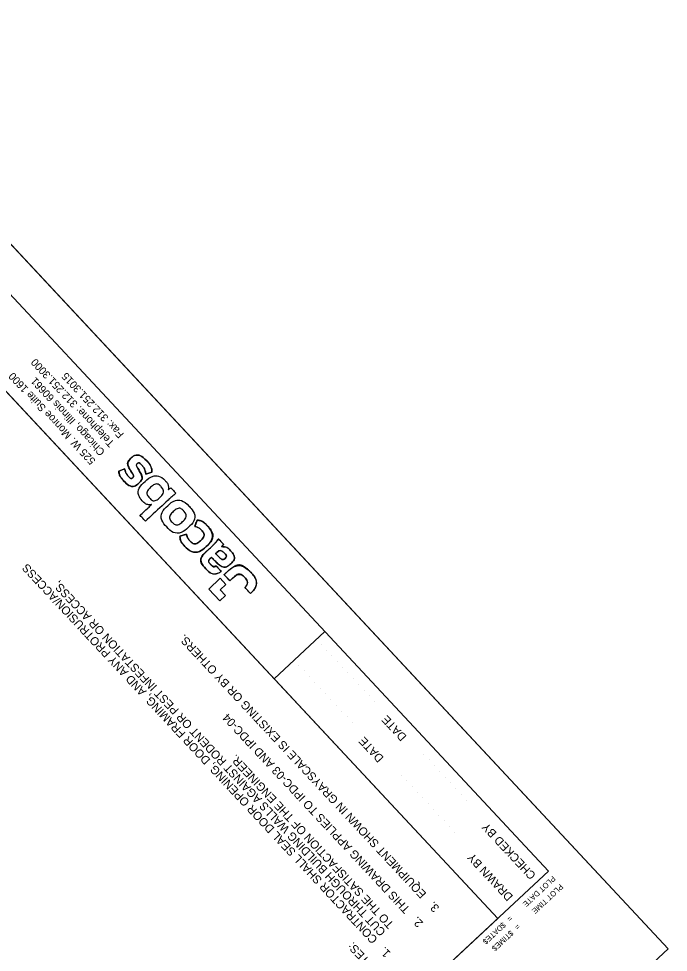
# Model space of a CAD drawing. Extents: x 1121979 to 1130574, y 1838676 to 1848573.
# Drawn here: x 1129668.15 to 1129686.91, y 1839365.55 to 1839392.53 of the extents above; entities that cross this region are included whole.
import ezdxf

# ---------------------------------------------------------------- set-up
doc = ezdxf.new("R2010")
doc.units = 0
for name, color, linetype in [('GE-LOG-JEG', 7, 'Continuous'), ('GE-NOT-Notes', 7, 'Continuous'), ('GE-SHT-Clip Border', 7, 'Continuous'), ('GE-SHT-General', 7, 'Continuous'), ('GE-SHT-Plot Border', 7, 'Continuous'), ('HS_Title', 7, 'Continuous')]:
    doc.layers.add(name, color=color, linetype=linetype)

msp = doc.modelspace()

# ---------------------------------------------------------------- linework, layer by layer
at = {"layer": 'GE-LOG-JEG'}
for p, q in [((1129671.632, 1839379.468), (1129671.579, 1839379.556)), ((1129671.212, 1839379.521), (1129671.037, 1839379.46)), ((1129671.38, 1839379.472), (1129671.437, 1839379.377)), ((1129671.82, 1839379.365), (1129671.995, 1839379.429)), ((1129673.304, 1839378.04), (1129673.233, 1839377.862)), ((1129672.999, 1839377.632), (1129672.806, 1839377.575)), ((1129674.064, 1839377.344), (1129673.917, 1839377.5)), ((1129673.745, 1839377.301), (1129673.551, 1839377.12)), ((1129673.999, 1839376.559), (1129673.853, 1839376.716)), ((1129673.971, 1839376.362), (1129673.637, 1839376.05)), ((1129674.135, 1839376.186), (1129673.971, 1839376.362)), ((1129673.637, 1839376.05), (1129673.957, 1839375.707)), ((1129673.968, 1839376.03), (1129674.135, 1839376.186)), ((1129674.124, 1839375.862), (1129673.968, 1839376.03)), ((1129674.68, 1839376.092), (1129674.843, 1839375.917)), ((1129673.957, 1839375.707), (1129674.124, 1839375.862))]:
    msp.add_line(p, q, dxfattribs=at)
for points in [[(1129673.946, 1839376.961), (1129673.83, 1839377.074), (1129673.869, 1839377.11)], [(1129673.689, 1839376.942), (1129673.714, 1839376.966), (1129673.863, 1839376.821)], [(1129674.187, 1839376.563), (1129674.082, 1839376.465), (1129674.246, 1839376.289), (1129674.351, 1839376.387)], [(1129674.135, 1839376.186), (1129673.971, 1839376.362), (1129673.637, 1839376.05), (1129673.957, 1839375.707), (1129674.124, 1839375.862), (1129673.968, 1839376.03), (1129674.135, 1839376.186)]]:
    msp.add_lwpolyline(points, dxfattribs=at)
for points, degree in [([(1129671.848, 1839379.754), (1129671.7, 1839379.913), (1129671.514, 1839379.947), (1129671.395, 1839379.836), (1129671.292, 1839379.74), (1129671.288, 1839379.624), (1129671.38, 1839379.472), (1129671.38, 1839379.472), (1129671.437, 1839379.377), (1129671.437, 1839379.377), (1129671.466, 1839379.329), (1129671.468, 1839379.291), (1129671.445, 1839379.269), (1129671.414, 1839379.24), (1129671.366, 1839379.252), (1129671.32, 1839379.302), (1129671.268, 1839379.357), (1129671.235, 1839379.425), (1129671.212, 1839379.521), (1129671.212, 1839379.521), (1129671.037, 1839379.46), (1129671.037, 1839379.46), (1129671.049, 1839379.365), (1129671.098, 1839379.266), (1129671.178, 1839379.181), (1129671.323, 1839379.025), (1129671.497, 1839378.998), (1129671.622, 1839379.114), (1129671.72, 1839379.206), (1129671.723, 1839379.319), (1129671.632, 1839379.468), (1129671.632, 1839379.468), (1129671.579, 1839379.556), (1129671.579, 1839379.556), (1129671.543, 1839379.616), (1129671.542, 1839379.646), (1129671.571, 1839379.673), (1129671.602, 1839379.703), (1129671.653, 1839379.685), (1129671.712, 1839379.622), (1129671.76, 1839379.57), (1129671.803, 1839379.468), (1129671.82, 1839379.365), (1129671.82, 1839379.365), (1129671.995, 1839379.429), (1129671.995, 1839379.429), (1129671.995, 1839379.53), (1129671.939, 1839379.654), (1129671.848, 1839379.754)], 3), ([(1129671.848, 1839379.754), (1129671.7, 1839379.913), (1129671.514, 1839379.947), (1129671.395, 1839379.836), (1129671.292, 1839379.74), (1129671.288, 1839379.624), (1129671.38, 1839379.472)], 3), ([(1129671.579, 1839379.556), (1129671.543, 1839379.616), (1129671.542, 1839379.646), (1129671.571, 1839379.673), (1129671.602, 1839379.703), (1129671.653, 1839379.685), (1129671.712, 1839379.622), (1129671.76, 1839379.57), (1129671.803, 1839379.468), (1129671.82, 1839379.365)], 3), ([(1129671.995, 1839379.429), (1129671.995, 1839379.53), (1129671.939, 1839379.654), (1129671.848, 1839379.754)], 2), ([(1129671.037, 1839379.46), (1129671.049, 1839379.365), (1129671.098, 1839379.266), (1129671.178, 1839379.181), (1129671.323, 1839379.025), (1129671.497, 1839378.998), (1129671.622, 1839379.114), (1129671.72, 1839379.206), (1129671.723, 1839379.319), (1129671.632, 1839379.468)], 3), ([(1129671.437, 1839379.377), (1129671.466, 1839379.329), (1129671.468, 1839379.291), (1129671.445, 1839379.269), (1129671.414, 1839379.24), (1129671.366, 1839379.252), (1129671.32, 1839379.302), (1129671.268, 1839379.357), (1129671.235, 1839379.425), (1129671.212, 1839379.521)], 3), ([(1129672.379, 1839379.184), (1129672.243, 1839379.33), (1129672.003, 1839379.35), (1129671.799, 1839379.16), (1129671.602, 1839378.976), (1129671.588, 1839378.742), (1129671.729, 1839378.59), (1129671.806, 1839378.508), (1129671.899, 1839378.478), (1129671.993, 1839378.493), (1129671.993, 1839378.493), (1129671.654, 1839378.177), (1129671.654, 1839378.177), (1129671.654, 1839378.177), (1129671.809, 1839378.011), (1129671.809, 1839378.011), (1129671.809, 1839378.011), (1129672.512, 1839378.666), (1129672.512, 1839378.666), (1129672.57, 1839378.72), (1129672.623, 1839378.765), (1129672.689, 1839378.818), (1129672.689, 1839378.818), (1129672.543, 1839378.974), (1129672.543, 1839378.974), (1129672.517, 1839378.954), (1129672.489, 1839378.933), (1129672.46, 1839378.908), (1129672.481, 1839379.011), (1129672.449, 1839379.109), (1129672.379, 1839379.184), (1129672.379, 1839379.184), (1129672.379, 1839379.184), (1129672.379, 1839379.184)], 3), ([(1129672.379, 1839379.184), (1129672.243, 1839379.33), (1129672.003, 1839379.35), (1129671.799, 1839379.16), (1129671.602, 1839378.976), (1129671.588, 1839378.742), (1129671.729, 1839378.59), (1129671.806, 1839378.508), (1129671.899, 1839378.478), (1129671.993, 1839378.493), (1129671.993, 1839378.493), (1129671.654, 1839378.177), (1129671.654, 1839378.177), (1129671.654, 1839378.177), (1129671.809, 1839378.011), (1129671.809, 1839378.011), (1129671.809, 1839378.011), (1129672.512, 1839378.666), (1129672.512, 1839378.666), (1129672.57, 1839378.72), (1129672.623, 1839378.765), (1129672.689, 1839378.818), (1129672.689, 1839378.818), (1129672.543, 1839378.974), (1129672.543, 1839378.974), (1129672.517, 1839378.954), (1129672.489, 1839378.933), (1129672.46, 1839378.908), (1129672.481, 1839379.011), (1129672.449, 1839379.109), (1129672.379, 1839379.184), (1129672.379, 1839379.184), (1129672.379, 1839379.184), (1129672.379, 1839379.184)], 3), ([(1129672.265, 1839379.004), (1129672.347, 1839378.916), (1129672.336, 1839378.8), (1129672.229, 1839378.699), (1129672.122, 1839378.599), (1129672.005, 1839378.596), (1129671.923, 1839378.684), (1129671.841, 1839378.773), (1129671.852, 1839378.889), (1129671.959, 1839378.989), (1129672.066, 1839379.089), (1129672.183, 1839379.092), (1129672.265, 1839379.004), (1129672.265, 1839379.004), (1129672.265, 1839379.004), (1129672.265, 1839379.004)], 3), ([(1129672.265, 1839379.004), (1129672.347, 1839378.916), (1129672.336, 1839378.8), (1129672.229, 1839378.699), (1129672.122, 1839378.599), (1129672.005, 1839378.596), (1129671.923, 1839378.684), (1129671.841, 1839378.773), (1129671.852, 1839378.889), (1129671.959, 1839378.989), (1129672.066, 1839379.089), (1129672.183, 1839379.092), (1129672.265, 1839379.004), (1129672.265, 1839379.004), (1129672.265, 1839379.004), (1129672.265, 1839379.004)], 3), ([(1129673.075, 1839378.438), (1129672.9, 1839378.626), (1129672.651, 1839378.644), (1129672.453, 1839378.459), (1129672.255, 1839378.275), (1129672.25, 1839378.031), (1129672.425, 1839377.843), (1129672.597, 1839377.659), (1129672.855, 1839377.653), (1129673.042, 1839377.827), (1129673.234, 1839378.006), (1129673.247, 1839378.253), (1129673.075, 1839378.438), (1129673.075, 1839378.438), (1129673.075, 1839378.438), (1129673.075, 1839378.438)], 3), ([(1129673.075, 1839378.438), (1129672.9, 1839378.626), (1129672.651, 1839378.644), (1129672.453, 1839378.459), (1129672.255, 1839378.275), (1129672.25, 1839378.031), (1129672.425, 1839377.843), (1129672.597, 1839377.659), (1129672.855, 1839377.653), (1129673.042, 1839377.827), (1129673.234, 1839378.006), (1129673.247, 1839378.253), (1129673.075, 1839378.438), (1129673.075, 1839378.438), (1129673.075, 1839378.438), (1129673.075, 1839378.438)], 3), ([(1129672.919, 1839378.303), (1129673.001, 1839378.215), (1129672.99, 1839378.099), (1129672.882, 1839377.999), (1129672.775, 1839377.899), (1129672.658, 1839377.896), (1129672.576, 1839377.984), (1129672.494, 1839378.072), (1129672.505, 1839378.188), (1129672.612, 1839378.288), (1129672.72, 1839378.388), (1129672.837, 1839378.391), (1129672.919, 1839378.303), (1129672.919, 1839378.303), (1129672.919, 1839378.303), (1129672.919, 1839378.303)], 3), ([(1129672.919, 1839378.303), (1129673.001, 1839378.215), (1129672.99, 1839378.099), (1129672.882, 1839377.999), (1129672.775, 1839377.899), (1129672.658, 1839377.896), (1129672.576, 1839377.984), (1129672.494, 1839378.072), (1129672.505, 1839378.188), (1129672.612, 1839378.288), (1129672.72, 1839378.388), (1129672.837, 1839378.391), (1129672.919, 1839378.303), (1129672.919, 1839378.303), (1129672.919, 1839378.303), (1129672.919, 1839378.303)], 3), ([(1129673.586, 1839377.89), (1129673.508, 1839377.973), (1129673.399, 1839378.032), (1129673.304, 1839378.04), (1129673.304, 1839378.04), (1129673.233, 1839377.862), (1129673.233, 1839377.862), (1129673.305, 1839377.843), (1129673.38, 1839377.802), (1129673.422, 1839377.756), (1129673.51, 1839377.662), (1129673.502, 1839377.542), (1129673.399, 1839377.445), (1129673.298, 1839377.352), (1129673.176, 1839377.348), (1129673.079, 1839377.452), (1129673.039, 1839377.495), (1129673.011, 1839377.564), (1129672.999, 1839377.632), (1129672.999, 1839377.632), (1129672.806, 1839377.575), (1129672.806, 1839377.575), (1129672.809, 1839377.48), (1129672.853, 1839377.385), (1129672.928, 1839377.304), (1129673.123, 1839377.095), (1129673.385, 1839377.112), (1129673.558, 1839377.274), (1129673.756, 1839377.458), (1129673.768, 1839377.695), (1129673.586, 1839377.89), (1129673.586, 1839377.89), (1129673.586, 1839377.89), (1129673.586, 1839377.89)], 3), ([(1129673.586, 1839377.89), (1129673.508, 1839377.973), (1129673.399, 1839378.032), (1129673.304, 1839378.04)], 2), ([(1129672.806, 1839377.575), (1129672.809, 1839377.48), (1129672.853, 1839377.385), (1129672.928, 1839377.304), (1129673.123, 1839377.095), (1129673.385, 1839377.112), (1129673.558, 1839377.274), (1129673.756, 1839377.458), (1129673.768, 1839377.695), (1129673.586, 1839377.89)], 3), ([(1129673.233, 1839377.862), (1129673.305, 1839377.843), (1129673.38, 1839377.802), (1129673.422, 1839377.756), (1129673.51, 1839377.662), (1129673.502, 1839377.542), (1129673.399, 1839377.445), (1129673.298, 1839377.352), (1129673.176, 1839377.348), (1129673.079, 1839377.452), (1129673.039, 1839377.495), (1129673.011, 1839377.564), (1129672.999, 1839377.632)], 3), ([(1129674.064, 1839377.344), (1129674.064, 1839377.344), (1129673.917, 1839377.5), (1129673.917, 1839377.5), (1129673.878, 1839377.441), (1129673.803, 1839377.355), (1129673.745, 1839377.301), (1129673.745, 1839377.301), (1129673.551, 1839377.12), (1129673.551, 1839377.12), (1129673.401, 1839376.981), (1129673.396, 1839376.802), (1129673.549, 1839376.638), (1129673.714, 1839376.461), (1129673.898, 1839376.488), (1129673.999, 1839376.559), (1129673.999, 1839376.559), (1129673.853, 1839376.716), (1129673.853, 1839376.716), (1129673.804, 1839376.689), (1129673.746, 1839376.7), (1129673.69, 1839376.76), (1129673.635, 1839376.82), (1129673.629, 1839376.886), (1129673.689, 1839376.942), (1129673.689, 1839376.942), (1129673.714, 1839376.966), (1129673.714, 1839376.966), (1129673.714, 1839376.966), (1129673.863, 1839376.821), (1129673.863, 1839376.821), (1129674.021, 1839376.668), (1129674.163, 1839376.679), (1129674.271, 1839376.78), (1129674.388, 1839376.889), (1129674.381, 1839377.037), (1129674.263, 1839377.164), (1129674.175, 1839377.258), (1129674.073, 1839377.276), (1129674.007, 1839377.271), (1129674.03, 1839377.297), (1129674.05, 1839377.324), (1129674.064, 1839377.344), (1129674.064, 1839377.344), (1129674.064, 1839377.344), (1129674.064, 1839377.344)], 3), ([(1129673.917, 1839377.5), (1129673.878, 1839377.441), (1129673.803, 1839377.355), (1129673.745, 1839377.301)], 2), ([(1129673.551, 1839377.12), (1129673.401, 1839376.981), (1129673.396, 1839376.802), (1129673.549, 1839376.638), (1129673.714, 1839376.461), (1129673.898, 1839376.488), (1129673.999, 1839376.559)], 3), ([(1129673.869, 1839377.11), (1129673.95, 1839377.185), (1129674.04, 1839377.141), (1129674.092, 1839377.086), (1129674.145, 1839377.029), (1129674.152, 1839376.978), (1129674.107, 1839376.935), (1129674.067, 1839376.898), (1129674.014, 1839376.896), (1129673.946, 1839376.961), (1129673.946, 1839376.961), (1129673.83, 1839377.074), (1129673.83, 1839377.074), (1129673.83, 1839377.074), (1129673.869, 1839377.11), (1129673.869, 1839377.11)], 3), ([(1129673.863, 1839376.821), (1129674.021, 1839376.668), (1129674.163, 1839376.679), (1129674.271, 1839376.78), (1129674.388, 1839376.889), (1129674.381, 1839377.037), (1129674.263, 1839377.164), (1129674.175, 1839377.258), (1129674.073, 1839377.276), (1129674.007, 1839377.271)], 3), ([(1129673.869, 1839377.11), (1129673.95, 1839377.185), (1129674.04, 1839377.141), (1129674.092, 1839377.086), (1129674.145, 1839377.029), (1129674.152, 1839376.978), (1129674.107, 1839376.935), (1129674.067, 1839376.898), (1129674.014, 1839376.896), (1129673.946, 1839376.961)], 3), ([(1129674.007, 1839377.271), (1129674.03, 1839377.297), (1129674.05, 1839377.324), (1129674.064, 1839377.344)], 2), ([(1129673.853, 1839376.716), (1129673.804, 1839376.689), (1129673.746, 1839376.7), (1129673.69, 1839376.76), (1129673.635, 1839376.82), (1129673.629, 1839376.886), (1129673.689, 1839376.942)], 3), ([(1129674.844, 1839376.54), (1129674.655, 1839376.743), (1129674.385, 1839376.748), (1129674.187, 1839376.563), (1129674.187, 1839376.563), (1129674.082, 1839376.465), (1129674.082, 1839376.465), (1129674.082, 1839376.465), (1129674.246, 1839376.289), (1129674.246, 1839376.289), (1129674.246, 1839376.289), (1129674.351, 1839376.387), (1129674.351, 1839376.387), (1129674.455, 1839376.484), (1129674.582, 1839376.483), (1129674.675, 1839376.383), (1129674.763, 1839376.289), (1129674.755, 1839376.179), (1129674.68, 1839376.092), (1129674.68, 1839376.092), (1129674.843, 1839375.917), (1129674.843, 1839375.917), (1129675.017, 1839376.097), (1129675.023, 1839376.349), (1129674.844, 1839376.54), (1129674.844, 1839376.54), (1129674.844, 1839376.54), (1129674.844, 1839376.54)], 3), ([(1129674.844, 1839376.54), (1129674.655, 1839376.743), (1129674.385, 1839376.748), (1129674.187, 1839376.563)], 2), ([(1129674.351, 1839376.387), (1129674.455, 1839376.484), (1129674.582, 1839376.483), (1129674.675, 1839376.383), (1129674.763, 1839376.289), (1129674.755, 1839376.179), (1129674.68, 1839376.092)], 3), ([(1129674.843, 1839375.917), (1129675.017, 1839376.097), (1129675.023, 1839376.349), (1129674.844, 1839376.54)], 2)]:
    msp.add_open_spline(points, degree=degree, dxfattribs=at)
at = {"layer": 'GE-NOT-Notes'}
msp.add_line((1129686.907, 1839365.651), (1129640.533, 1839415.386), dxfattribs=at)
at = {"layer": 'GE-SHT-Clip Border'}
msp.add_lwpolyline([(1129652.729, 1839339.252), (1129609.766, 1839385.33), (1129639.021, 1839412.608), (1129681.985, 1839366.531)], close=True, dxfattribs=at)
msp.add_lwpolyline([(1129652.729, 1839339.252), (1129609.766, 1839385.33), (1129639.021, 1839412.608), (1129681.985, 1839366.531)], close=True, dxfattribs=at)
msp.add_lwpolyline([(1129652.729, 1839339.252), (1129609.766, 1839385.33), (1129639.021, 1839412.608), (1129681.985, 1839366.531)], close=True, dxfattribs=at)
at = {"layer": 'GE-SHT-General'}
for p, q in [((1129639.021, 1839412.608), (1129681.985, 1839366.531)), ((1129676.986, 1839374.824), (1129675.524, 1839373.46)), ((1129676.884, 1839374.454), (1129676.884, 1839374.454)), ((1129677.039, 1839374.288), (1129677.039, 1839374.288)), ((1129677.194, 1839374.122), (1129677.194, 1839374.122)), ((1129677.348, 1839373.957), (1129677.348, 1839373.957)), ((1129676.238, 1839373.851), (1129676.238, 1839373.851)), ((1129676.393, 1839373.685), (1129676.393, 1839373.685)), ((1129677.503, 1839373.791), (1129677.503, 1839373.791)), ((1129677.657, 1839373.625), (1129677.657, 1839373.625)), ((1129676.547, 1839373.52), (1129676.547, 1839373.52)), ((1129676.702, 1839373.354), (1129676.702, 1839373.354)), ((1129677.812, 1839373.459), (1129677.812, 1839373.459)), ((1129676.856, 1839373.188), (1129676.856, 1839373.188)), ((1129677.966, 1839373.293), (1129677.966, 1839373.293)), ((1129678.121, 1839373.128), (1129678.121, 1839373.128)), ((1129677.011, 1839373.022), (1129677.011, 1839373.022)), ((1129677.166, 1839372.856), (1129677.166, 1839372.856)), ((1129678.276, 1839372.962), (1129678.276, 1839372.962)), ((1129678.43, 1839372.796), (1129678.43, 1839372.796)), ((1129677.32, 1839372.691), (1129677.32, 1839372.691)), ((1129677.475, 1839372.525), (1129677.475, 1839372.525)), ((1129677.629, 1839372.359), (1129677.629, 1839372.359)), ((1129677.784, 1839372.193), (1129677.784, 1839372.193)), ((1129679.844, 1839371.28), (1129679.844, 1839371.28)), ((1129679.998, 1839371.114), (1129679.998, 1839371.114)), ((1129680.153, 1839370.948), (1129680.153, 1839370.948)), ((1129679.197, 1839370.677), (1129679.197, 1839370.677)), ((1129680.308, 1839370.783), (1129680.308, 1839370.783)), ((1129679.352, 1839370.511), (1129679.352, 1839370.511)), ((1129680.462, 1839370.617), (1129680.462, 1839370.617)), ((1129680.617, 1839370.451), (1129680.617, 1839370.451)), ((1129679.507, 1839370.346), (1129679.507, 1839370.346)), ((1129679.661, 1839370.18), (1129679.661, 1839370.18)), ((1129680.771, 1839370.285), (1129680.771, 1839370.285)), ((1129680.926, 1839370.119), (1129680.926, 1839370.119)), ((1129679.816, 1839370.014), (1129679.816, 1839370.014)), ((1129679.97, 1839369.848), (1129679.97, 1839369.848)), ((1129681.08, 1839369.954), (1129681.08, 1839369.954)), ((1129680.125, 1839369.683), (1129680.125, 1839369.683)), ((1129680.279, 1839369.517), (1129680.279, 1839369.517)), ((1129680.434, 1839369.351), (1129680.434, 1839369.351)), ((1129680.589, 1839369.185), (1129680.589, 1839369.185)), ((1129680.743, 1839369.019), (1129680.743, 1839369.019)), ((1129686.907, 1839365.651), (1129686.907, 1839365.651)), ((1129686.907, 1839365.651), (1129686.907, 1839365.651)), ((1129686.907, 1839365.651), (1129686.907, 1839365.651)), ((1129686.907, 1839365.651), (1129686.907, 1839365.651)), ((1129686.907, 1839365.651), (1129686.907, 1839365.651)), ((1129686.907, 1839365.651), (1129686.907, 1839365.651)), ((1129686.907, 1839365.651), (1129686.907, 1839365.651)), ((1129686.907, 1839365.651), (1129686.907, 1839365.651)), ((1129686.907, 1839365.651), (1129686.907, 1839365.651)), ((1129686.907, 1839365.651), (1129686.907, 1839365.651)), ((1129686.907, 1839365.651), (1129686.907, 1839365.651)), ((1129686.907, 1839365.651), (1129686.907, 1839365.651)), ((1129686.907, 1839365.651), (1129686.907, 1839365.651)), ((1129686.907, 1839365.651), (1129686.907, 1839365.651)), ((1129686.907, 1839365.651), (1129686.907, 1839365.651)), ((1129686.907, 1839365.651), (1129686.907, 1839365.651)), ((1129686.907, 1839365.651), (1129686.907, 1839365.651)), ((1129686.907, 1839365.651), (1129686.907, 1839365.651)), ((1129686.907, 1839365.651), (1129686.907, 1839365.651)), ((1129686.907, 1839365.651), (1129686.907, 1839365.651)), ((1129686.907, 1839365.651), (1129686.907, 1839365.651)), ((1129686.907, 1839365.651), (1129686.907, 1839365.651)), ((1129686.907, 1839365.651), (1129686.907, 1839365.651)), ((1129686.907, 1839365.651), (1129686.907, 1839365.651)), ((1129686.907, 1839365.651), (1129686.907, 1839365.651)), ((1129686.907, 1839365.651), (1129686.907, 1839365.651)), ((1129686.907, 1839365.651), (1129686.907, 1839365.651)), ((1129686.907, 1839365.651), (1129686.907, 1839365.651)), ((1129686.907, 1839365.651), (1129686.907, 1839365.651)), ((1129686.907, 1839365.651), (1129686.907, 1839365.651)), ((1129686.907, 1839365.651), (1129686.907, 1839365.651)), ((1129686.907, 1839365.651), (1129686.907, 1839365.651)), ((1129686.907, 1839365.651), (1129686.907, 1839365.651)), ((1129686.907, 1839365.651), (1129686.907, 1839365.651)), ((1129686.907, 1839365.651), (1129686.907, 1839365.651)), ((1129686.907, 1839365.651), (1129686.907, 1839365.651)), ((1129686.907, 1839365.651), (1129686.907, 1839365.651)), ((1129686.907, 1839365.651), (1129686.907, 1839365.651))]:
    msp.add_line(p, q, dxfattribs=at)
msp.add_lwpolyline([(1129652.729, 1839339.252), (1129609.766, 1839385.33), (1129640.484, 1839413.972), (1129683.448, 1839367.895)], close=True, dxfattribs=at)
at = {"layer": 'GE-SHT-Plot Border'}
msp.add_lwpolyline([(1129686.907, 1839365.651), (1129640.533, 1839415.386), (1129608.352, 1839385.379), (1129654.726, 1839335.645)], close=True, dxfattribs=at)

# ---------------------------------------------------------------- texts
at = {"layer": 'GE-LOG-JEG'}
for s, p in [('Telephone: 312.251.3000', (1129670.929, 1839380.278)), ('525 W. Monroe Suite 1600', (1129670.382, 1839379.768)), ('Fax: 312.251.3015', (1129671.202, 1839380.533)), ('Chicago, Illinois 60661', (1129670.655, 1839380.023))]:
    msp.add_text(s, height=0.22, rotation=132.9971, dxfattribs=at).set_placement(p)
at = {"layer": 'GE-NOT-Notes'}
for s, p in [('CONTRACTOR SHALL SEAL DOOR OPENING, DOOR FRAMING, AND ANY PROTRUSION/ACCESS', (1129678.529, 1839365.94)), ('CUT THROUGH BUILDING WALLS AGAINST RODENT OR PEST INFESTATION OR ACCESS, ', (1129678.763, 1839366.159)), ('EQUIPMENT SHOWN IN GRAYSCALE IS EXISTING OR BY OTHERS. ', (1129679.935, 1839367.251)), ('THIS DRAWING APPLIES TO IPDC-03 AND IPDC-04', (1129679.467, 1839366.814)), ('TO THE SATISFACTION OF THE ENGINEER.', (1129678.998, 1839366.377)), ('3.', (1129680.311, 1839366.849)), ('2.', (1129679.842, 1839366.412)), ('1.', (1129678.904, 1839365.538))]:
    msp.add_text(s, height=0.24, rotation=132.9971, dxfattribs=at).set_placement(p)
at = {"layer": 'GE-SHT-General'}
for s, height, rotation, p in [('DATE', 0.24, 132.9972, (1129679.367, 1839371.795)), ('DATE', 0.24, 132.9972, (1129678.705, 1839371.178)), ('CHECKED BY', 0.24, 132.9972, (1129683.099, 1839367.792)), ('DRAWN BY', 0.24, 132.9972, (1129682.438, 1839367.175)), ('PLOT DATE', 0.16, 222.9971, (1129683.56, 1839367.777)), ('PLOT TIME', 0.16, 222.9971, (1129683.78, 1839367.541)), ('=', 0.16, 222.9971, (1129682.322, 1839366.623)), ('$DATE$', 0.16, 222.9971, (1129682.123, 1839366.437)), ('=', 0.16, 222.9971, (1129682.542, 1839366.386)), ('$TIME$', 0.16, 222.9971, (1129682.344, 1839366.201))]:
    msp.add_text(s, height=height, rotation=rotation, dxfattribs=at).set_placement(p)
at = {"layer": 'HS_Title'}
msp.add_text('NOTES:', height=0.24, rotation=133.0067, dxfattribs=at).set_placement((1129678.616, 1839364.996))

doc.saveas('drawing.dxf')
